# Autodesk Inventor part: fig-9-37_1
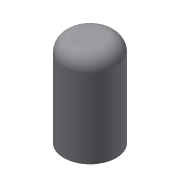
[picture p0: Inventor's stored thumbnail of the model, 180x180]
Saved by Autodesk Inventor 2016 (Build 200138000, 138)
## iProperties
Created: 2013-03
Part Number: fig-9-37_1
Material: Generic
Document SubType Name: Modeling
Designer: CADCIM
Density: 1 g/cm^3
Appearance: Default
Author: CADCIM
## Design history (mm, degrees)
sketch "Sketch1"
  geometry: C1 r 10 at (0, 0); 1 further point
  constraints: 1 centre point, 1 coincident
  dimensions: "d0" = 20 diameter of C1
extrude "Extrusion1" new body sketch "Sketch1" distance "d2" = 35; taper "d3" = 0 deg
fillet "Fillet1" dims "d4" = 5
shell "Shell1" dims "d5" = 2
body "Solid1"
